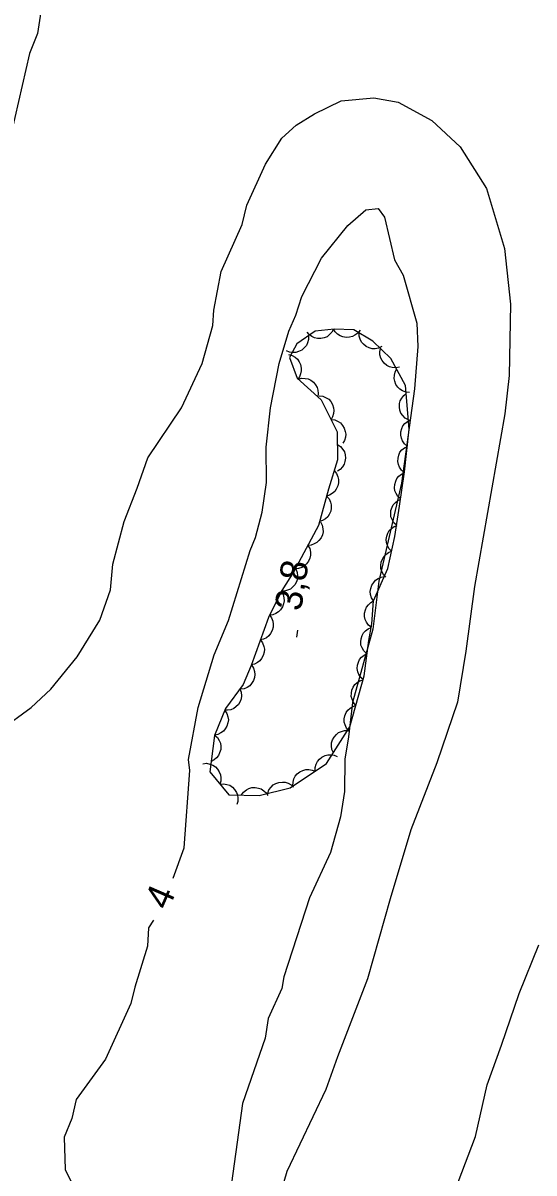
# Model space of a CAD drawing. Extents: x 282461 to 284471, y 5554090 to 5557646.
# Drawn here: x 283789.6 to 283846.7, y 5555029 to 5555157.5 of the extents above; entities that cross this region are included whole.
import ezdxf

# ---------------------------------------------------------------- set-up
doc = ezdxf.new("R2010")
doc.units = 0
for name, color, linetype in [('Niveau 1', 7, 'Continuous'), ('Niveau 2', 7, 'Continuous'), ('Niveau 3', 7, 'Continuous'), ('Niveau 44', 7, 'Continuous')]:
    doc.layers.add(name, color=color, linetype=linetype)

msp = doc.modelspace()

# ---------------------------------------------------------------- linework, layer by layer
at = {"layer": 'Niveau 1'}
for points in [[(283793.53, 5555171.34), (283791.21, 5555156.35), (283790.34, 5555154.11), (283788.28, 5555145.18)], [(283787.03, 5555078.48), (283790.52, 5555081.02), (283792.7, 5555083.07), (283795.67, 5555086.69), (283798.19, 5555090.78), (283799.4, 5555094.17), (283799.65, 5555097.04), (283800.93, 5555101.81), (283802.36, 5555105.52), (283803.57, 5555108.93), (283807.34, 5555114.5), (283809.65, 5555119.47), (283810.83, 5555123.72), (283810.95, 5555125.41), (283811.76, 5555129.74), (283814.12, 5555135.01), (283814.63, 5555137.15), (283816.71, 5555141.75), (283818.55, 5555144.63), (283820.15, 5555146.1), (283822.21, 5555147.35), (283825.18, 5555148.81), (283828.83, 5555149.14), (283831.56, 5555148.68), (283835.31, 5555146.63), (283838.49, 5555143.67)], [(283838.49, 5555143.67), (283841.43, 5555139.01), (283843.45, 5555132.32), (283844.1, 5555126.08), (283843.94, 5555118.14), (283843.47, 5555113.83), (283840.06, 5555094.56), (283839.11, 5555087.31), (283838.17, 5555081.64), (283835.86, 5555074.84), (283832.97, 5555067.36), (283830.65, 5555059.66), (283828.1, 5555050.7), (283824.75, 5555041.98), (283823.47, 5555038.35), (283819.1, 5555029.18), (283817.93, 5555025.21)], [(283838.24, 5555028), (283840.2, 5555033.1), (283841.49, 5555038.88), (283843.11, 5555043.3), (283845.07, 5555049.08), (283847.27, 5555054.52)]]:
    msp.add_lwpolyline(points, dxfattribs=at)
at = {"layer": 'Niveau 2'}
for points in [[(283806.4, 5555061.94), (283807.64, 5555065.35), (283808.27, 5555074), (283808.09, 5555075.22), (283809.2, 5555081.04), (283810.96, 5555086.9), (283812.59, 5555090.76), (283814.99, 5555098.58), (283815.58, 5555100.03), (283816.34, 5555102.84), (283816.84, 5555106.18), (283816.78, 5555110.12), (283817.28, 5555114.5), (283818.23, 5555119.48), (283819.32, 5555123.09), (283820.11, 5555124.87), (283820.78, 5555126.97), (283822.96, 5555131.25), (283825.93, 5555134.9), (283827.92, 5555136.62), (283829.32, 5555136.79), (283830.01, 5555135.81), (283831.15, 5555131.04), (283832.09, 5555129.34), (283833.65, 5555123.97), (283833.76, 5555121.37), (283833.38, 5555116.65), (283831.9, 5555106.09), (283829.37, 5555095.16), (283828.71, 5555089.78), (283826.43, 5555081.6), (283825.99, 5555077.74), (283825.59, 5555075.24), (283825.53, 5555071.63), (283825.11, 5555068.81), (283823.99, 5555064.84), (283821.64, 5555059.74), (283818.75, 5555050.94), (283818.55, 5555049.61), (283817.02, 5555046.27), (283816.67, 5555044.08), (283814.15, 5555036.78), (283812.61, 5555025.73)], [(283804.19, 5555057.25), (283803.65, 5555056.39), (283803.53, 5555054.34), (283802.11, 5555049.77), (283801.65, 5555047.95), (283798.82, 5555041.72), (283795.55, 5555037.24), (283795.06, 5555035.11), (283794.21, 5555033.03), (283794.33, 5555029.41), (283795.87, 5555026.24)]]:
    msp.add_lwpolyline(points, dxfattribs=at)
at = {"layer": 'Niveau 3'}
msp.add_line((283820.2, 5555088.88), (283820.32, 5555089.67), dxfattribs=at)
at = {"layer": 'Niveau 44'}
for points in [[(283828.8, 5555092.93), (283830.39, 5555096.55), (283831.16, 5555100.15), (283831.71, 5555103.53), (283832.25, 5555107.37), (283832.78, 5555112.13), (283832.37, 5555117.01), (283830.71, 5555120.01), (283828.7, 5555121.97), (283826.59, 5555123.23), (283824.38, 5555123.32), (283822.28, 5555123.07), (283820.2, 5555121.65), (283819.4, 5555120.13), (283820.24, 5555117.82), (283822.95, 5555115.41), (283824.74, 5555111.82), (283824.77, 5555108.69), (283823.76, 5555105.42), (283822.64, 5555101.35), (283819.9, 5555096.21), (283818.53, 5555094.11), (283817.04, 5555091.07), (283815.12, 5555085.71), (283814.21, 5555083.61), (283812.26, 5555080.92), (283811.02, 5555077.89), (283810.48, 5555073.82), (283812.6, 5555071.28), (283815.99, 5555071.2), (283819.47, 5555072.05), (283823.52, 5555074.76), (283826.16, 5555078.85), (283827.73, 5555084.56), (283828.26, 5555088.51), (283828.59, 5555090.37), (283828.8, 5555092.93)], [(283821.52, 5555122.55), (283821.53, 5555122.14), (283821.41, 5555121.76), (283821.28, 5555121.46), (283821.05, 5555121.2), (283820.77, 5555120.96), (283820.42, 5555120.81), (283820.12, 5555120.7), (283819.77, 5555120.7), (283819.41, 5555120.75), (283819.08, 5555120.88)], [(283824.32, 5555123.31), (283824.13, 5555122.95), (283823.85, 5555122.66), (283823.59, 5555122.46), (283823.27, 5555122.33), (283822.91, 5555122.25), (283822.53, 5555122.27), (283822.21, 5555122.32), (283821.9, 5555122.48), (283821.61, 5555122.69), (283821.37, 5555122.96)], [(283827.28, 5555123.2), (283827.04, 5555122.87), (283826.71, 5555122.63), (283826.43, 5555122.47), (283826.09, 5555122.4), (283825.72, 5555122.38), (283825.35, 5555122.46), (283825.05, 5555122.56), (283824.76, 5555122.76), (283824.5, 5555123.02), (283824.32, 5555123.32)], [(283829.73, 5555121.35), (283829.36, 5555121.18), (283828.96, 5555121.12), (283828.63, 5555121.12), (283828.3, 5555121.22), (283827.97, 5555121.37), (283827.68, 5555121.62), (283827.46, 5555121.85), (283827.31, 5555122.17), (283827.2, 5555122.52), (283827.18, 5555122.88)], [(283831.68, 5555119.06), (283831.28, 5555118.98), (283830.88, 5555119.02), (283830.56, 5555119.09), (283830.26, 5555119.26), (283829.97, 5555119.49), (283829.75, 5555119.8), (283829.59, 5555120.08), (283829.51, 5555120.42), (283829.5, 5555120.78), (283829.56, 5555121.13)], [(283819.28, 5555120.46), (283819.68, 5555120.36), (283820.02, 5555120.16), (283820.28, 5555119.95), (283820.48, 5555119.67), (283820.63, 5555119.34), (283820.7, 5555118.96), (283820.72, 5555118.64), (283820.64, 5555118.3), (283820.5, 5555117.97), (283820.29, 5555117.68)], [(283832.8, 5555116.23), (283832.39, 5555116.26), (283832.02, 5555116.41), (283831.74, 5555116.58), (283831.5, 5555116.83), (283831.29, 5555117.13), (283831.17, 5555117.49), (283831.09, 5555117.8), (283831.12, 5555118.15), (283831.21, 5555118.5), (283831.37, 5555118.82)], [(283820.35, 5555117.72), (283820.75, 5555117.82), (283821.16, 5555117.8), (283821.48, 5555117.74), (283821.79, 5555117.59), (283822.08, 5555117.37), (283822.32, 5555117.07), (283822.49, 5555116.8), (283822.58, 5555116.47), (283822.62, 5555116.1), (283822.57, 5555115.75)], [(283822.72, 5555115.86), (283823.13, 5555115.81), (283823.5, 5555115.64), (283823.78, 5555115.47), (283824, 5555115.21), (283824.2, 5555114.9), (283824.31, 5555114.53), (283824.37, 5555114.22), (283824.32, 5555113.87), (283824.22, 5555113.52), (283824.05, 5555113.21)], [(283832.69, 5555113.16), (283832.33, 5555113.36), (283832.05, 5555113.65), (283831.86, 5555113.92), (283831.75, 5555114.24), (283831.68, 5555114.6), (283831.71, 5555114.98), (283831.78, 5555115.3), (283831.94, 5555115.6), (283832.17, 5555115.89), (283832.44, 5555116.12)], [(283824.05, 5555113.21), (283824.46, 5555113.16), (283824.82, 5555112.99), (283825.1, 5555112.82), (283825.33, 5555112.55), (283825.52, 5555112.24), (283825.63, 5555111.88), (283825.69, 5555111.56), (283825.65, 5555111.22), (283825.54, 5555110.87), (283825.37, 5555110.56)], [(283832.57, 5555110.21), (283832.25, 5555110.48), (283832.04, 5555110.82), (283831.9, 5555111.11), (283831.85, 5555111.46), (283831.85, 5555111.82), (283831.96, 5555112.19), (283832.08, 5555112.49), (283832.3, 5555112.75), (283832.58, 5555112.99), (283832.89, 5555113.16)], [(283824.75, 5555110.41), (283825.1, 5555110.18), (283825.35, 5555109.87), (283825.53, 5555109.59), (283825.62, 5555109.26), (283825.65, 5555108.89), (283825.59, 5555108.52), (283825.51, 5555108.21), (283825.32, 5555107.92), (283825.07, 5555107.64), (283824.78, 5555107.44)], [(283832.24, 5555107.26), (283831.92, 5555107.53), (283831.71, 5555107.87), (283831.57, 5555108.17), (283831.52, 5555108.51), (283831.53, 5555108.87), (283831.63, 5555109.24), (283831.75, 5555109.54), (283831.97, 5555109.81), (283832.25, 5555110.05), (283832.57, 5555110.21)], [(283824.4, 5555107.5), (283824.66, 5555107.18), (283824.81, 5555106.8), (283824.89, 5555106.49), (283824.88, 5555106.14), (283824.8, 5555105.78), (283824.63, 5555105.44), (283824.45, 5555105.17), (283824.18, 5555104.95), (283823.87, 5555104.77), (283823.53, 5555104.66)], [(283831.82, 5555104.33), (283831.52, 5555104.6), (283831.31, 5555104.95), (283831.18, 5555105.25), (283831.14, 5555105.59), (283831.16, 5555105.96), (283831.27, 5555106.32), (283831.4, 5555106.61), (283831.63, 5555106.88), (283831.92, 5555107.11), (283832.24, 5555107.26)], [(283823.55, 5555104.66), (283823.82, 5555104.34), (283823.98, 5555103.97), (283824.07, 5555103.66), (283824.07, 5555103.31), (283824, 5555102.95), (283823.84, 5555102.61), (283823.67, 5555102.33), (283823.41, 5555102.1), (283823.1, 5555101.91), (283822.76, 5555101.8)], [(283831.36, 5555101.4), (283831.06, 5555101.68), (283830.86, 5555102.03), (283830.74, 5555102.33), (283830.71, 5555102.68), (283830.73, 5555103.04), (283830.86, 5555103.4), (283830.99, 5555103.69), (283831.23, 5555103.95), (283831.52, 5555104.17), (283831.84, 5555104.32)], [(283822.86, 5555101.76), (283823.05, 5555101.39), (283823.13, 5555101), (283823.15, 5555100.67), (283823.07, 5555100.33), (283822.92, 5555100), (283822.69, 5555099.7), (283822.47, 5555099.47), (283822.16, 5555099.3), (283821.82, 5555099.18), (283821.46, 5555099.14)], [(283830.8, 5555098.48), (283830.52, 5555098.78), (283830.34, 5555099.14), (283830.23, 5555099.45), (283830.21, 5555099.8), (283830.26, 5555100.16), (283830.4, 5555100.51), (283830.55, 5555100.8), (283830.79, 5555101.04), (283831.09, 5555101.25), (283831.42, 5555101.38)], [(283821.46, 5555099.14), (283821.66, 5555098.78), (283821.73, 5555098.38), (283821.75, 5555098.06), (283821.67, 5555097.72), (283821.53, 5555097.38), (283821.3, 5555097.08), (283821.07, 5555096.85), (283820.77, 5555096.68), (283820.42, 5555096.56), (283820.07, 5555096.52)], [(283830.18, 5555095.58), (283829.9, 5555095.88), (283829.72, 5555096.24), (283829.61, 5555096.55), (283829.59, 5555096.9), (283829.64, 5555097.26), (283829.78, 5555097.61), (283829.93, 5555097.9), (283830.17, 5555098.14), (283830.47, 5555098.35), (283830.8, 5555098.48)], [(283820.09, 5555096.51), (283820.25, 5555096.13), (283820.3, 5555095.73), (283820.29, 5555095.4), (283820.18, 5555095.07), (283820, 5555094.75), (283819.75, 5555094.47), (283819.5, 5555094.26), (283819.19, 5555094.12), (283818.83, 5555094.03), (283818.47, 5555094.02)], [(283828.8, 5555092.93), (283828.58, 5555093.28), (283828.47, 5555093.67), (283828.43, 5555093.99), (283828.48, 5555094.33), (283828.6, 5555094.68), (283828.81, 5555095), (283829.01, 5555095.25), (283829.31, 5555095.44), (283829.64, 5555095.58), (283829.99, 5555095.65)], [(283818.48, 5555094.02), (283818.69, 5555093.66), (283818.78, 5555093.27), (283818.81, 5555092.94), (283818.74, 5555092.6), (283818.61, 5555092.26), (283818.39, 5555091.95), (283818.17, 5555091.71), (283817.87, 5555091.54), (283817.53, 5555091.4), (283817.18, 5555091.35)], [(283828.56, 5555089.97), (283828.24, 5555090.23), (283828.01, 5555090.56), (283827.86, 5555090.86), (283827.8, 5555091.2), (283827.8, 5555091.56), (283827.89, 5555091.93), (283828, 5555092.23), (283828.22, 5555092.51), (283828.49, 5555092.76), (283828.8, 5555092.93)], [(283817.15, 5555091.37), (283817.39, 5555091.04), (283817.52, 5555090.66), (283817.59, 5555090.34), (283817.56, 5555089.99), (283817.47, 5555089.64), (283817.28, 5555089.31), (283817.1, 5555089.04), (283816.82, 5555088.83), (283816.49, 5555088.66), (283816.15, 5555088.58)], [(283828, 5555087.06), (283827.71, 5555087.35), (283827.51, 5555087.7), (283827.39, 5555088), (283827.36, 5555088.35), (283827.4, 5555088.71), (283827.52, 5555089.07), (283827.66, 5555089.36), (283827.9, 5555089.61), (283828.2, 5555089.83), (283828.52, 5555089.98)], [(283816.15, 5555088.58), (283816.39, 5555088.24), (283816.52, 5555087.86), (283816.59, 5555087.54), (283816.56, 5555087.2), (283816.47, 5555086.84), (283816.28, 5555086.51), (283816.09, 5555086.25), (283815.82, 5555086.04), (283815.49, 5555085.87), (283815.15, 5555085.78)], [(283827.67, 5555084.11), (283827.36, 5555084.38), (283827.15, 5555084.73), (283827.02, 5555085.03), (283826.98, 5555085.37), (283826.99, 5555085.74), (283827.11, 5555086.1), (283827.23, 5555086.39), (283827.46, 5555086.66), (283827.75, 5555086.89), (283828.06, 5555087.05)], [(283815.15, 5555085.78), (283815.37, 5555085.43), (283815.48, 5555085.05), (283815.53, 5555084.72), (283815.47, 5555084.38), (283815.36, 5555084.03), (283815.15, 5555083.71), (283814.95, 5555083.46), (283814.66, 5555083.27), (283814.32, 5555083.13), (283813.97, 5555083.06)], [(283826.82, 5555081.26), (283826.55, 5555081.58), (283826.39, 5555081.94), (283826.3, 5555082.26), (283826.31, 5555082.61), (283826.37, 5555082.96), (283826.53, 5555083.31), (283826.7, 5555083.58), (283826.96, 5555083.81), (283827.27, 5555084.01), (283827.61, 5555084.12)], [(283813.86, 5555083.12), (283814, 5555082.74), (283814.02, 5555082.34), (283814, 5555082.01), (283813.87, 5555081.69), (283813.68, 5555081.37), (283813.41, 5555081.11), (283813.16, 5555080.91), (283812.83, 5555080.78), (283812.47, 5555080.71), (283812.12, 5555080.72)], [(283826.04, 5555078.4), (283825.77, 5555078.72), (283825.61, 5555079.08), (283825.52, 5555079.4), (283825.52, 5555079.75), (283825.59, 5555080.1), (283825.75, 5555080.45), (283825.91, 5555080.72), (283826.17, 5555080.95), (283826.49, 5555081.15), (283826.82, 5555081.26)], [(283812.17, 5555080.7), (283812.4, 5555080.35), (283812.51, 5555079.97), (283812.56, 5555079.64), (283812.52, 5555079.3), (283812.41, 5555078.95), (283812.21, 5555078.63), (283812.01, 5555078.37), (283811.73, 5555078.18), (283811.39, 5555078.02), (283811.04, 5555077.95)], [(283824.3, 5555075.97), (283824.14, 5555076.35), (283824.09, 5555076.75), (283824.1, 5555077.07), (283824.21, 5555077.4), (283824.38, 5555077.73), (283824.64, 5555078.01), (283824.88, 5555078.22), (283825.2, 5555078.36), (283825.55, 5555078.45), (283825.91, 5555078.46)], [(283811.03, 5555077.95), (283811.34, 5555077.68), (283811.55, 5555077.34), (283811.68, 5555077.04), (283811.72, 5555076.69), (283811.71, 5555076.33), (283811.59, 5555075.97), (283811.47, 5555075.67), (283811.24, 5555075.41), (283810.96, 5555075.17), (283810.64, 5555075.01)], [(283809.71, 5555074.74), (283810.12, 5555074.79), (283810.51, 5555074.71), (283810.82, 5555074.6), (283811.11, 5555074.4), (283811.36, 5555074.14), (283811.55, 5555073.82), (283811.69, 5555073.52), (283811.73, 5555073.18), (283811.71, 5555072.81), (283811.61, 5555072.47)], [(283822.25, 5555073.91), (283822.25, 5555074.32), (283822.37, 5555074.71), (283822.51, 5555075), (283822.74, 5555075.26), (283823.02, 5555075.49), (283823.37, 5555075.65), (283823.67, 5555075.75), (283824.02, 5555075.75), (283824.38, 5555075.69), (283824.71, 5555075.56)], [(283819.78, 5555072.26), (283819.79, 5555072.67), (283819.9, 5555073.06), (283820.04, 5555073.35), (283820.27, 5555073.61), (283820.56, 5555073.84), (283820.9, 5555074), (283821.21, 5555074.1), (283821.56, 5555074.1), (283821.92, 5555074.04), (283822.25, 5555073.91)], [(283811.61, 5555072.47), (283812.02, 5555072.51), (283812.41, 5555072.43), (283812.72, 5555072.33), (283813.01, 5555072.13), (283813.26, 5555071.87), (283813.46, 5555071.54), (283813.59, 5555071.25), (283813.63, 5555070.9), (283813.61, 5555070.53), (283813.51, 5555070.19)], [(283814.02, 5555071.25), (283814.26, 5555071.58), (283814.58, 5555071.83), (283814.86, 5555071.99), (283815.2, 5555072.07), (283815.56, 5555072.1), (283815.93, 5555072.02), (283816.24, 5555071.93), (283816.53, 5555071.73), (283816.79, 5555071.48), (283816.98, 5555071.18)], [(283816.96, 5555071.44), (283817.1, 5555071.82), (283817.34, 5555072.14), (283817.57, 5555072.37), (283817.88, 5555072.54), (283818.22, 5555072.66), (283818.6, 5555072.68), (283818.92, 5555072.67), (283819.25, 5555072.56), (283819.57, 5555072.38), (283819.84, 5555072.14)]]:
    msp.add_lwpolyline(points, dxfattribs=at)

# ---------------------------------------------------------------- texts
at = {"layer": 'Niveau 2'}
msp.add_text('4', height=3, rotation=66.5571, dxfattribs=at).set_placement((283805.83, 5555058.27))
at = {"layer": 'Niveau 3'}
msp.add_text('3,8  ', height=3, rotation=81.0957, dxfattribs=at).set_placement((283820.68, 5555091.72))

doc.saveas('drawing.dxf')
